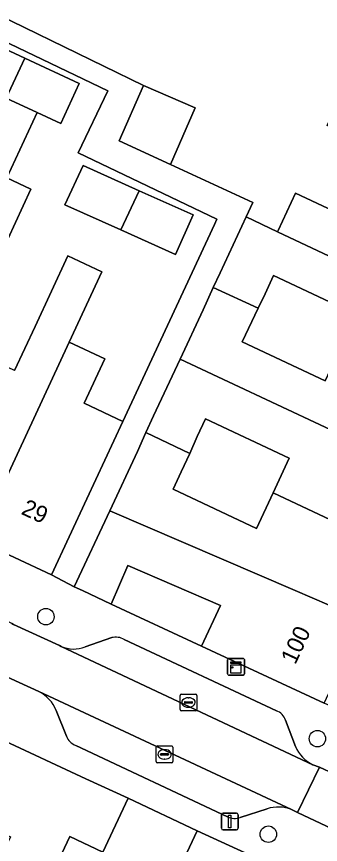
# Model space of a CAD drawing. Extents: x 159817 to 160765, y 380688 to 381638.
# Drawn here: x 160042.82 to 160060.94, y 381234.89 to 381284.17 of the extents above; entities that cross this region are included whole.
import ezdxf

# ---------------------------------------------------------------- set-up
doc = ezdxf.new("R2010")
doc.units = 0
for name, color, linetype in [('IMGEO_Boom', 7, 'Continuous'), ('IMGEO_Erf', 7, 'Continuous'), ('IMGEO_Kast', 7, 'Continuous'), ('IMGEO_Kolk', 7, 'Continuous'), ('IMGEO_Lichtmast', 7, 'Continuous'), ('IMGEO_Muur', 7, 'Continuous'), ('IMGEO_Pand', 7, 'Continuous'), ('IMGEO_Pand_nummerreeks', 7, 'Continuous'), ('IMGEO_Parkeervlak_open', 7, 'Continuous'), ('IMGEO_Rijbaan_lokaal_open', 7, 'Continuous'), ('IMGEO_Voetpad_open', 7, 'Continuous')]:
    doc.layers.add(name, color=color, linetype=linetype)

msp = doc.modelspace()

# ---------------------------------------------------------------- linework, layer by layer
at = {"layer": 'IMGEO_Boom'}
for centre in [(160044.572, 381248.449), (160060.763, 381241.189), (160057.837, 381235.503)]:
    msp.add_circle(centre, 0.489, dxfattribs=at)
at = {"layer": 'IMGEO_Erf'}
for points in [[(160038.546, 381285.838), (160050.389, 381280.071), (160053.476, 381278.724), (160052.007, 381275.357), (160056.916, 381273.099), (160056.514, 381272.239), (160058.376, 381271.363), (160058.412, 381271.44), (160059.45, 381273.656), (160064.586, 381271.252), (160065.493, 381273.189), (160066.473, 381275.282), (160061.338, 381277.685), (160062.349, 381279.844), (160063.433, 381282.16), (160068.595, 381279.743), (160069.491, 381281.657), (160070.462, 381283.731), (160065.286, 381286.154)], [(160042.704, 381263.107), (160043.925, 381265.728), (160045.877, 381269.918), (160047.913, 381268.97), (160045.961, 381264.78), (160048.083, 381263.792), (160046.853, 381261.151), (160049.165, 381260.074), (160054.622, 381271.788), (160054.767, 381272.112), (160046.498, 381276.065), (160048.26, 381279.75), (160039.455, 381283.959)], [(160040.315, 381283.07), (160043.311, 381281.687), (160046.557, 381280.189), (160045.457, 381277.805), (160044.049, 381278.455), (160042.238, 381274.565), (160043.682, 381273.892), (160041.837, 381269.931)], [(160043.823, 381230.722), (160046.005, 381235.357), (160047.975, 381234.442), (160049.48, 381237.64), (160046.955, 381238.804), (160041.843, 381241.188), (160040.235, 381237.74), (160039.629, 381236.689), (160042.454, 381235.339), (160040.895, 381232.075)], [(160057.89, 381233.73), (160053.601, 381235.7), (160052.088, 381232.486), (160055.443, 381230.907), (160053.272, 381226.294), (160051.101, 381221.683), (160047.771, 381223.25), (160046.276, 381220.074), (160044.781, 381216.898), (160048.175, 381215.3), (160046.025, 381210.732), (160043.874, 381206.163), (160040.489, 381207.757), (160039.007, 381204.608), (160037.525, 381201.46), (160040.922, 381199.861), (160038.765, 381195.278), (160036.608, 381190.697), (160033.22, 381192.292), (160031.696, 381189.056), (160035.794, 381187.126), (160036.497, 381186.883), (160037.238, 381186.827)]]:
    msp.add_lwpolyline(points, dxfattribs=at)
for points in [[(160046.804, 381275.296), (160050.134, 381273.802), (160053.354, 381272.357), (160052.301, 381270.009), (160049.048, 381271.468), (160045.702, 381272.969)], [(160062.248, 381264.669), (160061.671, 381264.939), (160062.5, 381266.71), (160058.149, 381268.747), (160057.643, 381267.666), (160057.228, 381266.803), (160056.278, 381264.809), (160061.229, 381262.491), (160062.172, 381264.507)], [(160052.164, 381256.029), (160057.126, 381253.706), (160058.119, 381255.828), (160059.086, 381257.893), (160054.091, 381260.231), (160053.599, 381259.179), (160053.146, 381258.17), (160052.648, 381257.063)], [(160048.471, 381249.2), (160053.846, 381246.702), (160054.98, 381249.123), (160049.459, 381251.498)]]:
    msp.add_lwpolyline(points, close=True, dxfattribs=at)
at = {"layer": 'IMGEO_Kast'}
for p, q in [((160055.408, 381245.042), (160055.408, 381245.883)), ((160055.408, 381245.883), (160055.408, 381245.042)), ((160055.483, 381245.967), (160056.324, 381245.967)), ((160056.324, 381245.967), (160055.483, 381245.967)), ((160056.408, 381245.892), (160056.408, 381245.051)), ((160056.408, 381245.051), (160056.408, 381245.892)), ((160056.333, 381244.967), (160055.492, 381244.967)), ((160055.492, 381244.967), (160056.333, 381244.967))]:
    msp.add_line(p, q, dxfattribs=at)
for points in [[(160055.603, 381245.757), (160056.203, 381245.757), (160056.203, 381245.672), (160055.603, 381245.672), (160055.603, 381245.757)], [(160055.603, 381245.582), (160056.203, 381245.582), (160056.203, 381245.093), (160055.603, 381245.093), (160055.603, 381245.582)]]:
    msp.add_lwpolyline(points, dxfattribs=at)
msp.add_circle((160055.687, 381245.431), 0.0377, dxfattribs=at)
for centre, start, end in [((160055.486, 381245.889), 92.4484, 184.2845), ((160055.486, 381245.889), 92.4484, 184.2845), ((160056.33, 381245.889), 2.4484, 94.2845), ((160056.33, 381245.889), 2.4484, 94.2845), ((160055.486, 381245.045), 182.4484, 274.2845), ((160055.486, 381245.045), 182.4484, 274.2845), ((160056.33, 381245.045), 272.4484, 4.2845), ((160056.33, 381245.045), 272.4484, 4.2845)]:
    msp.add_arc(centre, 0.0779, start, end, dxfattribs=at)
at = {"layer": 'IMGEO_Kolk'}
for p, q in [((160052.574, 381242.915), (160052.574, 381243.767)), ((160052.649, 381243.841), (160053.501, 381243.841)), ((160053.062, 381243.621), (160053.087, 381243.621)), ((160053.575, 381243.767), (160053.575, 381242.915)), ((160052.833, 381243.335), (160052.833, 381243.347)), ((160053.271, 381243.298), (160052.873, 381243.298)), ((160052.876, 381243.384), (160053.274, 381243.384)), ((160053.317, 381243.347), (160053.317, 381243.335)), ((160053.501, 381242.841), (160052.649, 381242.841)), ((160053.085, 381243.061), (160053.06, 381243.061)), ((160051.148, 381239.828), (160051.148, 381240.68)), ((160051.223, 381240.754), (160052.075, 381240.754)), ((160052.149, 381240.68), (160052.149, 381239.828)), ((160051.407, 381240.248), (160051.407, 381240.26)), ((160051.845, 381240.211), (160051.447, 381240.211)), ((160051.45, 381240.297), (160051.848, 381240.297)), ((160051.636, 381240.534), (160051.661, 381240.534)), ((160051.891, 381240.26), (160051.891, 381240.248)), ((160052.075, 381239.754), (160051.223, 381239.754)), ((160051.659, 381239.974), (160051.634, 381239.974))]:
    msp.add_line(p, q, dxfattribs=at)
for points in [[(160052.574, 381242.915), (160052.574, 381243.767)], [(160052.649, 381243.841), (160053.501, 381243.841)], [(160053.575, 381243.767), (160053.575, 381242.915)], [(160053.501, 381242.841), (160052.649, 381242.841)], [(160051.148, 381239.828), (160051.148, 381240.68)], [(160051.223, 381240.754), (160052.075, 381240.754)], [(160052.149, 381240.68), (160052.149, 381239.828)], [(160052.075, 381239.754), (160051.223, 381239.754)]]:
    msp.add_lwpolyline(points, dxfattribs=at)
for centre, radius, start, end in [((160052.651, 381243.765), 0.0765, 91.552, 178.448), ((160052.651, 381243.765), 0.0765, 91.552, 178.448), ((160053.499, 381243.765), 0.0765, 1.552, 88.448), ((160053.499, 381243.765), 0.0765, 1.552, 88.448), ((160052.873, 381243.344), 0.0403, 85.8775, 175.7526), ((160052.87, 381243.334), 0.0366, 178.938, 274.7102), ((160053.274, 381243.341), 0.043, 264.8664, 352.4533), ((160053.278, 381243.346), 0.0386, 1.7309, 96.639), ((160052.651, 381242.917), 0.0765, 181.552, 268.448), ((160052.651, 381242.917), 0.0765, 181.552, 268.448), ((160053.499, 381242.917), 0.0765, 271.552, 358.448), ((160053.499, 381242.917), 0.0765, 271.552, 358.448), ((160051.225, 381240.678), 0.0765, 91.552, 178.448), ((160051.225, 381240.678), 0.0765, 91.552, 178.448), ((160052.073, 381240.678), 0.0765, 1.552, 88.448), ((160052.073, 381240.678), 0.0765, 1.552, 88.448), ((160051.447, 381240.257), 0.0403, 85.8775, 175.7526), ((160051.444, 381240.247), 0.0366, 178.938, 274.7102), ((160051.848, 381240.254), 0.043, 264.8664, 352.4533), ((160051.852, 381240.259), 0.0386, 1.7309, 96.639), ((160051.225, 381239.83), 0.0765, 181.552, 268.448), ((160051.225, 381239.83), 0.0765, 181.552, 268.448), ((160052.073, 381239.83), 0.0765, 271.552, 358.448), ((160052.073, 381239.83), 0.0765, 271.552, 358.448)]:
    msp.add_arc(centre, radius, start, end, dxfattribs=at)
for centre, major_axis, ratio, start_param, end_param in [((160053.061, 381243.341), (-0.387, 0.002), 0.722429, 4.712389, 7.853982), ((160053.086, 381243.341), (-0.39, 0.002), 0.717154, 1.570796, 4.712389), ((160051.635, 381240.254), (-0.387, 0.002), 0.722429, 4.712389, 7.853982), ((160051.66, 381240.254), (-0.39, 0.002), 0.717154, 1.570796, 4.712389)]:
    msp.add_ellipse(centre, major_axis=major_axis, ratio=ratio, start_param=start_param, end_param=end_param, dxfattribs=at)
at = {"layer": 'IMGEO_Lichtmast'}
for p, q in [((160055.139, 381236.759), (160055.929, 381236.759)), ((160055.929, 381236.759), (160055.139, 381236.759)), ((160055.039, 381235.859), (160055.039, 381236.659)), ((160055.039, 381236.659), (160055.039, 381235.859)), ((160056.029, 381236.659), (160056.029, 381235.859)), ((160056.029, 381235.859), (160056.029, 381236.659)), ((160055.929, 381235.759), (160055.139, 381235.759)), ((160055.139, 381235.759), (160055.929, 381235.759))]:
    msp.add_line(p, q, dxfattribs=at)
msp.add_lwpolyline([(160055.459, 381236.634), (160055.609, 381236.634), (160055.609, 381235.884), (160055.459, 381235.884), (160055.459, 381236.634)], dxfattribs=at)
for centre, start, end in [((160055.139, 381236.659), 90, 180), ((160055.139, 381236.659), 90, 180), ((160055.929, 381236.659), 0, 90), ((160055.929, 381236.659), 360, 90), ((160055.139, 381235.859), 180, 270), ((160055.139, 381235.859), 180, 270), ((160055.929, 381235.859), 270, 0), ((160055.929, 381235.859), 270, 0)]:
    msp.add_arc(centre, 0.1, start, end, dxfattribs=at)
at = {"layer": 'IMGEO_Muur'}
msp.add_lwpolyline([(160046.955, 381238.804), (160049.48, 381237.64)], dxfattribs=at)
at = {"layer": 'IMGEO_Pand'}
for points in [[(160042.203, 381279.307), (160043.311, 381281.687), (160040.315, 381283.07), (160039.091, 381280.744)], [(160046.557, 381280.189), (160043.311, 381281.687), (160042.203, 381279.307), (160044.049, 381278.455), (160045.457, 381277.805)], [(160053.476, 381278.724), (160050.389, 381280.071), (160048.946, 381276.765), (160052.007, 381275.357)], [(160044.049, 381278.455), (160042.203, 381279.307), (160037.307, 381268.804), (160038.973, 381268.028), (160040.212, 381270.688), (160041.837, 381269.931), (160043.682, 381273.892), (160042.238, 381274.565)], [(160049.048, 381271.468), (160050.134, 381273.802), (160046.804, 381275.296), (160045.702, 381272.969)], [(160049.048, 381271.468), (160052.301, 381270.009), (160053.354, 381272.357), (160050.134, 381273.802)], [(160065.493, 381273.189), (160064.586, 381271.252), (160059.45, 381273.656), (160058.412, 381271.44), (160058.376, 381271.363), (160070.371, 381265.72), (160072.355, 381269.959)], [(160070.371, 381265.72), (160058.376, 381271.363), (160056.514, 381272.239), (160054.961, 381268.921), (160054.556, 381268.044), (160057.228, 381266.803), (160057.643, 381267.666), (160058.149, 381268.747), (160062.5, 381266.71), (160061.671, 381264.939), (160062.248, 381264.669), (160062.172, 381264.507), (160068.441, 381261.596), (160068.515, 381261.756)], [(160036.147, 381255.011), (160040.475, 381252.996), (160045.841, 381264.521), (160045.961, 381264.78), (160047.913, 381268.97), (160045.877, 381269.918), (160043.925, 381265.728), (160042.704, 381263.107), (160040.414, 381264.173), (160039.251, 381261.675)], [(160066.985, 381257.032), (160069.074, 381261.494), (160068.515, 381261.756), (160068.441, 381261.596), (160062.172, 381264.507), (160061.229, 381262.491), (160056.278, 381264.809), (160057.228, 381266.803), (160054.556, 381268.044), (160053.945, 381266.721), (160052.57, 381263.784)], [(160049.165, 381260.074), (160046.853, 381261.151), (160048.083, 381263.792), (160045.961, 381264.78), (160045.841, 381264.521), (160040.475, 381252.996), (160044.91, 381250.931), (160047.021, 381255.464)], [(160066.985, 381257.032), (160052.57, 381263.784), (160050.987, 381260.402), (160050.533, 381259.401), (160053.146, 381258.17), (160053.599, 381259.179), (160054.091, 381260.231), (160059.086, 381257.893), (160058.119, 381255.828), (160064.92, 381252.625), (160065.066, 381252.933)], [(160050.533, 381259.401), (160050.03, 381258.289), (160048.377, 381254.758), (160059.44, 381250), (160063.49, 381248.262), (160064.302, 381250), (160065.564, 381252.7), (160065.066, 381252.933), (160064.92, 381252.625), (160058.119, 381255.828), (160057.126, 381253.706), (160052.164, 381256.029), (160052.648, 381257.063), (160053.146, 381258.17)], [(160063.49, 381248.262), (160059.44, 381250), (160048.377, 381254.758), (160046.257, 381250.229), (160046.75, 381250), (160048.471, 381249.2), (160049.459, 381251.498), (160054.98, 381249.123), (160053.846, 381246.702), (160061.17, 381243.297)], [(160046.484, 381229.486), (160053.272, 381226.294), (160055.443, 381230.907), (160052.088, 381232.486), (160053.601, 381235.7), (160049.48, 381237.64), (160047.975, 381234.442), (160046.005, 381235.357), (160043.823, 381230.722)]]:
    msp.add_lwpolyline(points, close=True, dxfattribs=at)
at = {"layer": 'IMGEO_Parkeervlak_open'}
for points in [[(160048.495, 381247.2), (160046.917, 381246.652)], [(160058.315, 381242.843), (160049.248, 381247.098)], [(160045.486, 381246.679), (160060.496, 381239.637)], [(160059.207, 381236.967), (160044.148, 381243.99)], [(160045.185, 381242.868), (160045.798, 381241.329)], [(160059.449, 381240.713), (160058.852, 381242.289)], [(160046.35, 381240.785), (160055.405, 381236.537)], [(160056.164, 381236.497), (160057.775, 381237.017)]]:
    msp.add_lwpolyline(points, dxfattribs=at)
for centre, radius, start, end in [((160048.735, 381246.141), 1.086, 61.7987, 102.7729), ((160046.234, 381248.404), 1.88, 246.5462, 291.2919), ((160043.254, 381242.123), 2.07, 21.0851, 64.4057), ((160058.047, 381242.046), 0.841, 16.8008, 71.4137), ((160046.671, 381241.663), 0.934, 200.9145, 249.9219), ((160061.44, 381241.603), 2.18, 204.0784, 244.3564), ((160058.422, 381235.004), 2.115, 68.1963, 107.8042), ((160055.834, 381237.453), 1.012, 244.9216, 289.0449)]:
    msp.add_arc(centre, radius, start, end, dxfattribs=at)
at = {"layer": 'IMGEO_Rijbaan_lokaal_open'}
msp.add_lwpolyline([(160016.056, 381257.166), (160041.303, 381245.289), (160044.148, 381243.99), (160059.207, 381236.967), (160059.583, 381236.797), (160060.879, 381239.493), (160060.496, 381239.637), (160045.486, 381246.679), (160045.378, 381246.73), (160042.643, 381247.988), (160042.541, 381248.036), (160017.433, 381259.824), (160017.333, 381259.871)], close=True, dxfattribs=at)
msp.add_lwpolyline([(160062.588, 381238.706), (160060.879, 381239.493), (160059.583, 381236.797), (160063.03, 381235.175)], dxfattribs=at)
at = {"layer": 'IMGEO_Voetpad_open'}
for points in [[(160039.455, 381283.959), (160048.26, 381279.75), (160046.498, 381276.065), (160054.767, 381272.112), (160054.622, 381271.788), (160049.165, 381260.074), (160047.021, 381255.464), (160044.91, 381250.931), (160046.257, 381250.229), (160048.377, 381254.758), (160050.03, 381258.289), (160050.533, 381259.401), (160050.987, 381260.402), (160052.57, 381263.784), (160053.945, 381266.721), (160054.556, 381268.044), (160054.961, 381268.921), (160056.514, 381272.239), (160056.916, 381273.099), (160052.007, 381275.357), (160048.946, 381276.765), (160050.389, 381280.071), (160038.546, 381285.838)], [(160060.496, 381239.637), (160060.879, 381239.493), (160062.588, 381238.706), (160064.796, 381241.634), (160061.17, 381243.297), (160053.846, 381246.702), (160048.471, 381249.2), (160046.75, 381250), (160046.257, 381250.229), (160044.91, 381250.931), (160040.475, 381252.996), (160036.147, 381255.011), (160031.821, 381257.025), (160027.495, 381259.04), (160023.169, 381261.054)], [(160042.541, 381248.036), (160042.643, 381247.988), (160045.378, 381246.73), (160045.486, 381246.679)], [(160046.917, 381246.652), (160048.495, 381247.2)], [(160049.248, 381247.098), (160058.315, 381242.843)], [(160044.148, 381243.99), (160041.303, 381245.289)], [(160045.798, 381241.329), (160045.185, 381242.868)], [(160058.852, 381242.289), (160059.449, 381240.713)], [(160041.843, 381241.188), (160046.955, 381238.804), (160049.48, 381237.64), (160053.601, 381235.7), (160057.89, 381233.73)], [(160055.405, 381236.537), (160046.35, 381240.785)], [(160057.775, 381237.017), (160056.164, 381236.497)], [(160059.448, 381229.882), (160063.03, 381235.175), (160059.583, 381236.797), (160059.207, 381236.967)]]:
    msp.add_lwpolyline(points, dxfattribs=at)
for centre, radius, start, end in [((160048.735, 381246.141), 1.086, 61.7987, 102.7729), ((160046.234, 381248.404), 1.88, 246.5462, 291.2919), ((160043.254, 381242.123), 2.07, 21.0851, 64.4057), ((160058.047, 381242.046), 0.841, 16.8008, 71.4137), ((160046.671, 381241.663), 0.934, 200.9145, 249.9219), ((160061.44, 381241.603), 2.18, 204.0784, 244.3564), ((160058.422, 381235.004), 2.115, 68.1963, 107.8042), ((160055.834, 381237.453), 1.012, 244.9216, 289.0449)]:
    msp.add_arc(centre, radius, start, end, dxfattribs=at)

# ---------------------------------------------------------------- texts
at = {"layer": 'IMGEO_Pand_nummerreeks'}
for s, rotation, p in [('29', 335.0305, (160043.042, 381254.581)), ('100', 64.9562, (160059.442, 381245.551))]:
    msp.add_text(s, height=1, rotation=rotation, dxfattribs=at).set_placement(p)

doc.saveas('drawing.dxf')
